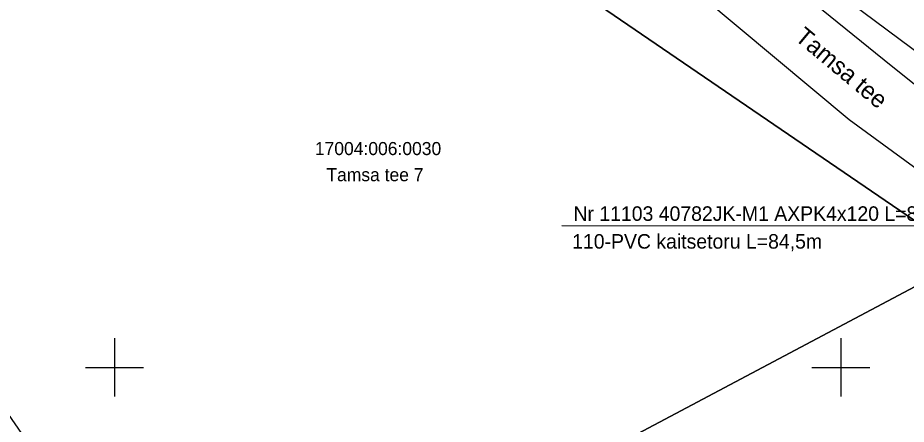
# Model space of a CAD drawing. Extents: x 643977 to 644381, y 6457457 to 6457867.
# Drawn here: x 644193.3 to 644254.5, y 6457546.1 to 6457574.1 of the extents above; entities that cross this region are included whole.
import ezdxf

# ---------------------------------------------------------------- set-up
doc = ezdxf.new("R2010")
doc.units = 0
for name, color, linetype in [('005 MPO EE @ 1 (2)', 7, 'Continuous'), ('007 PIIR1 EE', 7, 'Continuous'), ('TEE', 7, 'Continuous'), ('VORK', 7, 'Continuous')]:
    doc.layers.add(name, color=color, linetype=linetype)

msp = doc.modelspace()

# ---------------------------------------------------------------- linework, layer by layer
at = {"layer": '005 MPO EE @ 1 (2)'}
for points in [[(644165.209, 6457630.911), (644174.337, 6457623.878), (644186.272, 6457614.624), (644201.035, 6457604.979), (644215.289, 6457597.386), (644225.394, 6457591.42), (644240.377, 6457581.381), (644253.475, 6457570.785), (644267.864, 6457559.308)], [(644223.424, 6457587.828), (644237.787, 6457577.75), (644250.576, 6457567.066), (644264.806, 6457556.67)]]:
    msp.add_lwpolyline(points, dxfattribs=at)
at = {"layer": '007 PIIR1 EE'}
for points in [[(644212.727, 6457604.721), (644212.787, 6457603.384), (644212.635, 6457602.989), (644212.886, 6457602.359), (644220.606, 6457597.153), (644222.47, 6457596.063), (644231.114, 6457590.695), (644237.777, 6457585.353), (644242.629, 6457581.344), (644246.678, 6457578.098), (644259.713, 6457568.388), (644262.891, 6457566.699), (644271.921, 6457560.313), (644279.137, 6457556.219), (644280.27, 6457555.988)], [(644212.727, 6457604.721), (644212.787, 6457603.384), (644212.635, 6457602.989), (644212.886, 6457602.359), (644220.606, 6457597.153), (644222.47, 6457596.063), (644231.114, 6457590.695), (644237.777, 6457585.353), (644242.629, 6457581.344), (644246.678, 6457578.098), (644259.713, 6457568.388), (644262.891, 6457566.699), (644271.921, 6457560.313), (644279.137, 6457556.219), (644280.27, 6457555.988)], [(644230.795, 6457559.763), (644261.004, 6457559.737), (644266.084, 6457564.289)]]:
    msp.add_lwpolyline(points, dxfattribs=at)
at = {"layer": 'TEE'}
msp.add_lwpolyline([(644119.21, 6457655.5), (644137.18, 6457639.57), (644176.94, 6457610.8), (644193.44, 6457599.42), (644220.94, 6457583.42), (644258.83, 6457557.54), (644299.64, 6457526.51), (644330.13, 6457505.12), (644351.66, 6457500.83), (644373.13, 6457501.25), (644368.81, 6457508.24), (644366.6, 6457513.63), (644352.78, 6457513.35), (644335.16, 6457516.88), (644304.29, 6457538.7), (644233.94, 6457592.97), (644213.34, 6457605.08), (644212.32, 6457605.7), (644192.23, 6457620.22), (644172.44, 6457634.51), (644128.57, 6457664.58), (644105.62, 6457695.4)], dxfattribs=at)
for points in [[(644187.08, 6457554.88), (644204.95, 6457528.94), (644258.83, 6457557.54), (644220.94, 6457583.42), (644193.44, 6457599.42), (644191.21, 6457575.04)], [(644258.83, 6457557.54), (644204.95, 6457528.94), (644209.32, 6457456.67), (644282.85, 6457490.46), (644299.64, 6457526.51)]]:
    msp.add_lwpolyline(points, close=True, dxfattribs=at)
at = {"layer": 'VORK'}
for p, q in [((644200, 6457552), (644200, 6457548)), ((644250, 6457552), (644250, 6457548)), ((644198, 6457550), (644202, 6457550)), ((644248, 6457550), (644252, 6457550))]:
    msp.add_line(p, q, dxfattribs=at)

# ---------------------------------------------------------------- texts
at = {"layer": '005 MPO EE @ 1 (2)'}
msp.add_text('Tamsa tee', height=1.2, rotation=320.12345, dxfattribs=at).set_placement((644246.77, 6457572.595))
at = {"layer": '007 PIIR1 EE'}
for s, p in [('Nr 11103 40782JK-M1 AXPK4x120 L=84,5m', (644231.595, 6457560.086)), ('110-PVC kaitsetoru L=84,5m', (644231.506, 6457558.173))]:
    msp.add_text(s, height=1, dxfattribs=at).set_placement(p)
at = {"layer": 'TEE'}
for s, p in [('17004:006:0030', (644213.791, 6457564.614)), ('Tamsa tee 7', (644214.583, 6457562.814))]:
    msp.add_text(s, height=0.9, dxfattribs=at).set_placement(p)

doc.saveas('drawing.dxf')
